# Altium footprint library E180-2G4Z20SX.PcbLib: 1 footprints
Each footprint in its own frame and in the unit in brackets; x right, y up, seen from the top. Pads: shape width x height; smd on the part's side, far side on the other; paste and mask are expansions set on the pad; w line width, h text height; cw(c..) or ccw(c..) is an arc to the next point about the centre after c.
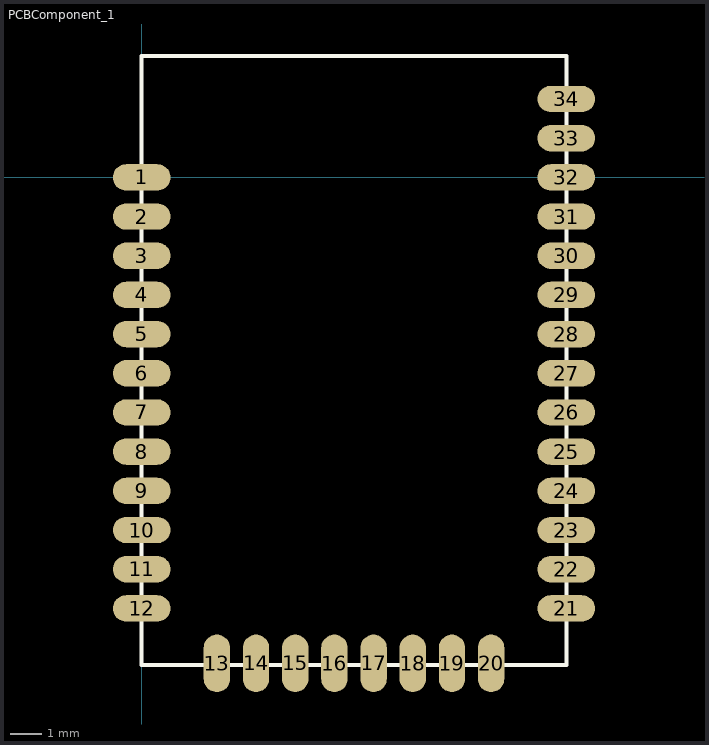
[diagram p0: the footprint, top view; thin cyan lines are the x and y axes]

## PCBComponent_1 [mil]
pads (34):
  oval 72x33 smd: 1(0,0) 2(0,-49.02) 3(0,-98.03) 4(0,-147.05) 5(0,-196.06) 6(0,-245.08) 7(0,-294.09) 8(0,-343.11) 9(0,-392.13) 10(0,-441.14) 11(0,-490.16) 12(0,-539.17) 21(531.11,-539.17) 22(531.11,-490.16) 23(531.11,-441.14) 24(531.11,-392.13) 25(531.11,-343.11) 26(531.11,-294.09) 27(531.11,-245.08) 28(531.11,-196.06) 29(531.11,-147.05) 30(531.11,-98.03) 31(531.11,-49.02) 32(531.11,0) 33(531.11,49.02) 34(531.11,98.03)
  oval 33x72 smd: 13(94,-608) 14(143.02,-608) 15(192.03,-608) 16(241.05,-608) 17(290.06,-608) 18(339.08,-608) 19(388.09,-608) 20(437.11,-608)
Top Overlay:
  lines w5: 0,-610 95,-610 531.11,-610 531.11,152.05 0,152.05 0,145 0,-535 0,-610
